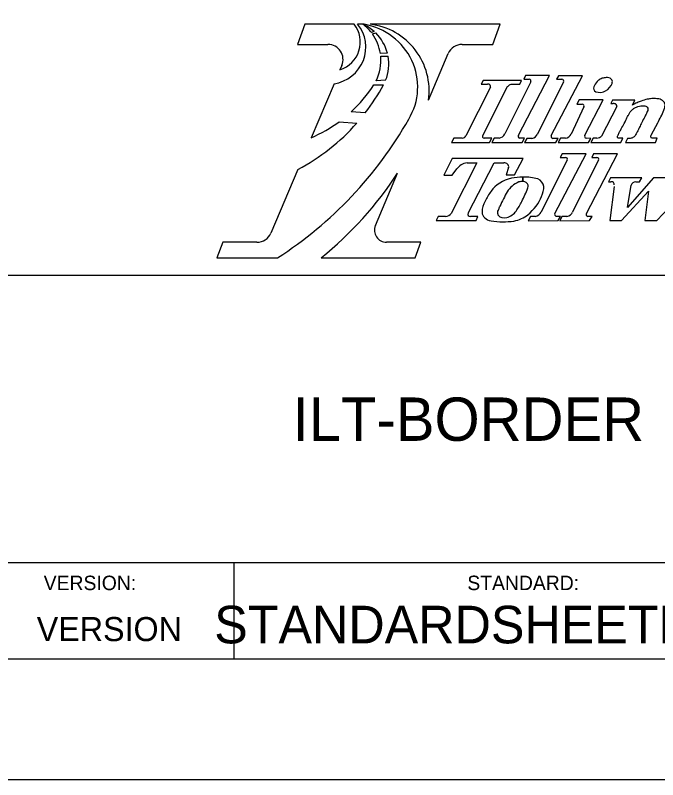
# Model space of a CAD drawing. Extents: x 0 to 2.83, y 0 to 1.83.
# Drawn here: x 2.4416 to 2.6636, y 0 to 0.2643 of the extents above; entities that cross this region are included whole.
import ezdxf

# ---------------------------------------------------------------- set-up
doc = ezdxf.new("R2010")
doc.units = 0
for name, color, linetype in [('SH_General_Details', 7, 'Continuous'), ('SH_General_Details_Sheet_Standard-ILTollway', 7, 'Continuous'), ('SH_General_Details_Title_Text-ILTollway', 7, 'Continuous'), ('SH_General_Details_Version_Text-ILTollway', 7, 'Continuous'), ('SH_Printer Plotting Border-ILTollway', 7, 'Continuous')]:
    doc.layers.add(name, color=color, linetype=linetype)

msp = doc.modelspace()

# ---------------------------------------------------------------- linework, layer by layer
at = {"layer": 'SH_General_Details'}
for p, q in [((2.541678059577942, 0.26125465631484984), (2.5391048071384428, 0.25424934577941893)), ((2.558770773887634, 0.26125307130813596), (2.541678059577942, 0.26125465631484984)), ((2.5617576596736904, 0.2612526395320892), (2.5599128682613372, 0.2612529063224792)), ((2.5622159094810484, 0.26125257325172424), (2.5617576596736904, 0.2612526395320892)), ((2.6092131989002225, 0.2612457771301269), (2.564246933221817, 0.26125227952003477)), ((2.6066432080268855, 0.25424934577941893), (2.6092131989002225, 0.2612457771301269)), ((2.5656805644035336, 0.2587088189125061), (2.564693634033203, 0.2583604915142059)), ((2.5650607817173, 0.2578687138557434), (2.5662091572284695, 0.25821166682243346)), ((2.5391048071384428, 0.25424934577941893), (2.5496910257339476, 0.25424934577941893)), ((2.5960569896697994, 0.25424934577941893), (2.6066432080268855, 0.25424934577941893)), ((2.570235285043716, 0.25119200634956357), (2.567815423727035, 0.251082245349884)), ((2.567924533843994, 0.2501808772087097), (2.5704507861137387, 0.25021086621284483)), ((2.584443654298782, 0.23498173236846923), (2.5912613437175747, 0.25107288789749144)), ((2.5544875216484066, 0.2470111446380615), (2.5538310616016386, 0.24545995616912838)), ((2.551788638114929, 0.24063379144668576), (2.5439024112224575, 0.221998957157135)), ((2.569615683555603, 0.24183801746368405), (2.5663216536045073, 0.24171894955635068)), ((2.616512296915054, 0.24179491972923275), (2.6032718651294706, 0.24179491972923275)), ((2.6197487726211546, 0.2413310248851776), (2.610752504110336, 0.22328553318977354)), ((2.615985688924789, 0.24053008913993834), (2.616512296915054, 0.24179491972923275)), ((2.6311086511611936, 0.24128882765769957), (2.622112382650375, 0.2232433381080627)), ((2.5655231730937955, 0.24031608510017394), (2.5688893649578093, 0.24028897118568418)), ((2.6058492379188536, 0.23947303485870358), (2.5973743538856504, 0.22265382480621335)), ((2.603179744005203, 0.22279209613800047), (2.6117820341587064, 0.23965211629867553)), ((2.613987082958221, 0.24053468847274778), (2.615985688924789, 0.24053008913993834)), ((2.6381201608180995, 0.23271397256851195), (2.633689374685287, 0.22326657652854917)), ((2.6494769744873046, 0.23273907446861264), (2.6442469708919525, 0.2225763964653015)), ((2.647989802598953, 0.2350050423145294), (2.6474070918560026, 0.23379013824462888)), ((2.6474070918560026, 0.23379013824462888), (2.648289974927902, 0.23379013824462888)), ((2.655788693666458, 0.2350050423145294), (2.647989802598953, 0.2350050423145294)), ((2.6549143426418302, 0.233294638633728), (2.655788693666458, 0.2350050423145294)), ((2.56256064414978, 0.23056123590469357), (2.5576849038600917, 0.23094110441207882)), ((2.5535774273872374, 0.22753960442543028), (2.559652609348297, 0.22704168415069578)), ((2.6615555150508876, 0.22308809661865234), (2.6636318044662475, 0.22710824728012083)), ((2.5931374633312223, 0.22180414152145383), (2.59234472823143, 0.22033744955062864)), ((2.59234472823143, 0.22033744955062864), (2.605503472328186, 0.22033744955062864)), ((2.5960391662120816, 0.2218161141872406), (2.5931374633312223, 0.22180414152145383)), ((2.6062812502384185, 0.22180450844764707), (2.603693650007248, 0.22180450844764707)), ((2.605503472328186, 0.22033744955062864), (2.6062812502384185, 0.22180450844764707)), ((2.607087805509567, 0.2218036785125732), (2.6062950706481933, 0.22033698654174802)), ((2.6062950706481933, 0.22033698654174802), (2.6168223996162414, 0.22032778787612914)), ((2.608808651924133, 0.2218008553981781), (2.607087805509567, 0.2218036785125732)), ((2.6176034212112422, 0.22180262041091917), (2.6160084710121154, 0.22181677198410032)), ((2.6168223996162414, 0.22032778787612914), (2.6176034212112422, 0.22180262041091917)), ((2.618447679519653, 0.2217614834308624), (2.6176549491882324, 0.22029479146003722)), ((2.6176549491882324, 0.22029479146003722), (2.6284404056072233, 0.22029142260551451)), ((2.6201685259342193, 0.22175866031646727), (2.618447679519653, 0.2217614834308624)), ((2.6292331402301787, 0.2217581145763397), (2.6273683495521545, 0.2217745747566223)), ((2.6284404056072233, 0.22029142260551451), (2.6292331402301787, 0.2217581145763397)), ((2.6300077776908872, 0.22183038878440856), (2.629215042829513, 0.22036369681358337)), ((2.629231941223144, 0.22031802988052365), (2.6397115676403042, 0.22031637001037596)), ((2.6317455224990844, 0.22178189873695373), (2.6300246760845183, 0.22178472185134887)), ((2.640502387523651, 0.22178071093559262), (2.6389453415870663, 0.22179781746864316)), ((2.6397115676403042, 0.22031637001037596), (2.640502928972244, 0.22178052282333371)), ((2.6412836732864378, 0.22180444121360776), (2.6404826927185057, 0.22033670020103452)), ((2.6404826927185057, 0.22033670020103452), (2.650853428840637, 0.22033670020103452)), ((2.642634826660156, 0.22180444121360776), (2.6412836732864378, 0.22180444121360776)), ((2.6515525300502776, 0.221801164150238), (2.6502094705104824, 0.221801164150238)), ((2.650853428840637, 0.22033670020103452), (2.6515525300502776, 0.221801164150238)), ((2.6531976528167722, 0.22174590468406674), (2.652547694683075, 0.22033670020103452)), ((2.652547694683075, 0.22033670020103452), (2.662856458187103, 0.22033670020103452)), ((2.6634214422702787, 0.2218007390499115), (2.6617628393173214, 0.22181180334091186)), ((2.662856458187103, 0.22033670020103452), (2.6634214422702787, 0.2218007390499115)), ((2.6323300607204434, 0.21430038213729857), (2.6233337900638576, 0.19625489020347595)), ((2.6432246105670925, 0.21430038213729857), (2.6342283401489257, 0.19625489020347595)), ((2.598115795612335, 0.1958784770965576), (2.6070817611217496, 0.2133110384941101)), ((2.6070817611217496, 0.2133110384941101), (2.610442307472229, 0.2133110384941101)), ((2.5392720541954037, 0.21105761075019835), (2.529944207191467, 0.18901628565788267)), ((2.5660758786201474, 0.19162998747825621), (2.573748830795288, 0.20973973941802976)), ((2.592641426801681, 0.20907231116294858), (2.594264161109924, 0.21120603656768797)), ((2.6170039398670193, 0.2083940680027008), (2.6170039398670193, 0.20687558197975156)), ((2.6170039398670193, 0.20687558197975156), (2.6170039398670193, 0.2083940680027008)), ((2.6666739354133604, 0.2080908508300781), (2.6621581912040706, 0.2080908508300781)), ((2.663346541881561, 0.19334409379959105), (2.6746359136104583, 0.20542692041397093)), ((2.6196690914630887, 0.19477303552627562), (2.6188763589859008, 0.193306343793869)), ((2.6188763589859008, 0.193306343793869), (2.6292116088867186, 0.19333077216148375)), ((2.6213899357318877, 0.19477021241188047), (2.6196690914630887, 0.19477303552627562)), ((2.630071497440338, 0.19479352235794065), (2.6285897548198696, 0.1947861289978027)), ((2.6292116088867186, 0.19333077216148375), (2.630071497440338, 0.19479352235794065)), ((2.6305636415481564, 0.19477303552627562), (2.6297709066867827, 0.193306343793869)), ((2.6297709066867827, 0.193306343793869), (2.6401061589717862, 0.19333077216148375)), ((2.6322844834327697, 0.19477021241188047), (2.6305636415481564, 0.19477303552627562)), ((2.6409660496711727, 0.19479352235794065), (2.639484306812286, 0.1947861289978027)), ((2.6401061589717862, 0.19333077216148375), (2.6409660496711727, 0.19479352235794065)), ((2.6591873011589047, 0.19334409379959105), (2.663346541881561, 0.19334409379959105)), ((2.513288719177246, 0.18583782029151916), (2.5113223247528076, 0.1804845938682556)), ((2.5251477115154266, 0.18583782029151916), (2.513288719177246, 0.18583782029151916)), ((2.581771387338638, 0.18583782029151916), (2.5699123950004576, 0.18583782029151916)), ((2.579804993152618, 0.1804845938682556), (2.581771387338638, 0.18583782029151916)), ((2.5113223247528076, 0.1804845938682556), (2.53227757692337, 0.1804845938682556)), ((2.547344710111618, 0.1804845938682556), (2.579804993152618, 0.1804845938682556)), ((2.7916666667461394, 0.17433751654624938), (2.4316674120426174, 0.17433751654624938)), ((2.7916666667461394, 0.07499986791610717), (2.4316674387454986, 0.07499986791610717)), ((2.517257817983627, 0.04166668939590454), (2.517257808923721, 0.07499986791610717))]:
    msp.add_line(p, q, dxfattribs=at)
msp.add_lwpolyline([(0.1666666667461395, 0.0416666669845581), (0.1666666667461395, 1.791666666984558), (2.7916666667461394, 1.791666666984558), (2.7916666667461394, 0.0416666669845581)], close=True, dxfattribs=at)
for points in [[(2.6155131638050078, 0.22285597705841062), (2.6262976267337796, 0.2434896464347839), (2.61800227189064, 0.2434869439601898)], [(2.61800227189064, 0.2434869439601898), (2.6173446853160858, 0.24223627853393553), (2.6191797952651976, 0.24223627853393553)], [(2.626873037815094, 0.22281378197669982), (2.6376575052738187, 0.24344744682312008), (2.629362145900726, 0.24344474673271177)], [(2.629362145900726, 0.24344474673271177), (2.628704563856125, 0.2421940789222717)], [(2.5663006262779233, 0.2417181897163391), (2.5663148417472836, 0.24171870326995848), (2.5663184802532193, 0.24171883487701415)], [(2.5663216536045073, 0.24171894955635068), (2.5663150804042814, 0.2417120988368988)], [(2.5663184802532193, 0.24171883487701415), (2.5663216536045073, 0.24171894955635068)], [(2.6032718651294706, 0.24179491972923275), (2.6026142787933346, 0.2405442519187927)], [(2.6026142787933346, 0.2405442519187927), (2.6048686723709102, 0.2405442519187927)], [(2.628704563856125, 0.2421940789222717), (2.6305396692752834, 0.2421940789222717)], [(2.636509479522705, 0.23505239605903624), (2.6357160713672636, 0.23361922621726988), (2.6375511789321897, 0.23361922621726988)], [(2.638450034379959, 0.22283702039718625), (2.644804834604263, 0.23505509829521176), (2.636509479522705, 0.23505239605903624)], [(2.612125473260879, 0.21171108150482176), (2.6113013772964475, 0.20911943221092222), (2.6141857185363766, 0.20911943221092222), (2.6171877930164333, 0.21477393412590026), (2.5925825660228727, 0.21477393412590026), (2.5896982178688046, 0.20907231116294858), (2.592641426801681, 0.20907231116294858)], [(2.6280944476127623, 0.19582533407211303), (2.6388789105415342, 0.21645900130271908), (2.6305835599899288, 0.21645630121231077)], [(2.6305835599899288, 0.21645630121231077), (2.629925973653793, 0.2152056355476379), (2.6317610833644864, 0.2152056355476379)], [(2.6389889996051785, 0.19582533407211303), (2.649773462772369, 0.21645900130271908), (2.641478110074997, 0.21645630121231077)], [(2.641478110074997, 0.21645630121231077), (2.6408205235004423, 0.2152056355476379), (2.6426556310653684, 0.2152056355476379)], [(2.5977626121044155, 0.21331319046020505), (2.601117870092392, 0.21331319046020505), (2.592229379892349, 0.19583135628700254)], [(2.6473037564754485, 0.20813842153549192), (2.64659074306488, 0.20675888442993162), (2.6474820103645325, 0.20675888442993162)], [(2.6560975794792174, 0.20675888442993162), (2.657345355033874, 0.20675888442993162), (2.6581772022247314, 0.20813842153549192), (2.6473037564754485, 0.20813842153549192)], [(2.6621581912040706, 0.2080908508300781), (2.6531861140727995, 0.1979108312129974)], [(2.6485515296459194, 0.20509393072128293), (2.6471255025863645, 0.19334409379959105), (2.651165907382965, 0.19334409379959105)], [(2.6531861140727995, 0.1979108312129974), (2.6544338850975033, 0.20561720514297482)], [(2.651165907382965, 0.19334409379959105), (2.660435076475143, 0.20352411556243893), (2.6591873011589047, 0.19334409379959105)], [(2.5902868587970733, 0.19474757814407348), (2.5877556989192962, 0.19474757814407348), (2.5871081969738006, 0.19333395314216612), (2.6008824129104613, 0.19333395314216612), (2.601529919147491, 0.19474757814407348), (2.5989987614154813, 0.19474757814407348)]]:
    msp.add_lwpolyline(points, dxfattribs=at)
for centre, radius, start, end in [((2.5507281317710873, 0.255099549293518), 0.010126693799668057, 287.8430702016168, 37.42003830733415), ((2.5556024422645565, 0.24746375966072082), 0.01510032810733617, 48.13245664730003, 65.94449523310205), ((2.5523351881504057, 0.24875107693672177), 0.015654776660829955, 37.86715463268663, 52.99453830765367), ((2.5614015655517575, 0.23816590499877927), 0.02326105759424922, 352.1321590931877, 82.97379849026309), ((2.5523351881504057, 0.24875107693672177), 0.015654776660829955, 8.563821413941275, 35.620851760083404), ((2.5556024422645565, 0.24746375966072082), 0.01510032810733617, 14.2940508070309, 45.378821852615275), ((2.5496910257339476, 0.24904101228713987), 0.005208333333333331, 337.0620105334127, 90), ((2.5960569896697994, 0.24904101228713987), 0.005208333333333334, 89.99999999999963, 157.0380282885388), ((2.5523351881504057, 0.24875107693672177), 0.015654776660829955, 333.3076244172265, 5.240307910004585), ((2.5556024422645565, 0.24746375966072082), 0.01510032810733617, 338.1265619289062, 10.481826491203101), ((2.5249901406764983, 0.26624088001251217), 0.04811467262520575, 312.80595253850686, 327.3971515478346), ((2.506296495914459, 0.2740884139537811), 0.07113557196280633, 322.2736785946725, 331.63145455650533), ((2.4574629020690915, 0.29661533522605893), 0.13814334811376, 302.79076806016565, 330.41292215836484), ((2.5249901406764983, 0.26624088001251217), 0.04811467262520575, 293.1454474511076, 306.45199352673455), ((2.506296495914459, 0.2740884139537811), 0.07113557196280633, 297.6170242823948, 318.5957779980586), ((2.469345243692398, 0.2774257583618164), 0.1244247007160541, 308.8203728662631, 327.04420513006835), ((2.5699123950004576, 0.19000448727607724), 0.004166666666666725, 157.03802828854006, 270), ((2.5251477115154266, 0.1910461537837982), 0.005208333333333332, 270.00000000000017, 337.0620105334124)]:
    msp.add_arc(centre, radius, start, end, dxfattribs=at)
for centre, major_axis, ratio, start_param, end_param in [((2.5495658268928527, 0.2532761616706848), (0.0132138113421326, 0), 0.9705854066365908, 4.8814113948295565, 6.954431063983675), ((2.5579672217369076, 0.23956523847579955), (0.022744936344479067, 0), 0.9705854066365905, 5.75331709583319, 7.666080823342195), ((2.566307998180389, 0.24171546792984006), (7.887166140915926e-06, 0), 0.9705854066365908, 2.778111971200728, 5.827459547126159), ((2.604906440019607, 0.23974349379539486), (0.0010015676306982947, -2.4531331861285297e-19), 0.8000752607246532, 5.938912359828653, 7.891702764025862), ((2.6190690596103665, 0.2416246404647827), (0.0007724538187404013, -1.8919661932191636e-19), 0.800075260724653, 5.788124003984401, 7.71013160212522), ((2.6304289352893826, 0.2415824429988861), (0.0007724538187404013, -1.8919661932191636e-19), 0.800075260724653, 5.788124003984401, 7.71013160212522), ((2.649391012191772, 0.2375553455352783), (-0.008237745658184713, 1.0088328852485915e-18), 0.8000752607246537, 5.657384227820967, 5.961923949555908), ((2.641774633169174, 0.24230186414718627), (0.006436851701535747, -1.5765739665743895e-18), 0.8000752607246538, 5.35994097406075, 5.975474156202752), ((2.643243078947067, 0.2390981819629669), (-0.00179891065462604, 2.2030301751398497e-19), 0.8000752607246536, 5.899852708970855, 7.2592592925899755), ((2.6436369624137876, 0.24040055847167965), (-0.003418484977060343, 4.1864366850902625e-19), 0.800075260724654, 1.1482793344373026, 2.20319774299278), ((2.637440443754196, 0.23300758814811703), (0.0007724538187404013, -1.8919661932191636e-19), 0.800075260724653, 5.788124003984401, 7.71013160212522), ((2.6484939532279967, 0.23298302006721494), (-0.0010292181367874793, 1.2604286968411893e-19), 0.8000752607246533, 2.840833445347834, 4.911898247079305), ((2.5958096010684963, 0.2231503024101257), (0.0016833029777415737, -4.122903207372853e-19), 0.8000752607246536, 4.8491919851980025, 5.905635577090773), ((2.603823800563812, 0.22242724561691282), (-0.0007891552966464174, 9.664365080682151e-20), 0.8000752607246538, 5.667079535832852, 7.688297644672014), ((2.607959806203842, 0.2240691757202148), (0.0029594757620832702, -7.2486250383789e-19), 0.8000752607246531, 5.00329646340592, 5.945866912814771), ((2.6163459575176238, 0.22251490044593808), (-0.0009355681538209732, 1.1457405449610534e-19), 0.8000752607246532, 5.810064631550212, 7.4849317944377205), ((2.619319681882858, 0.22402697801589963), (0.0029594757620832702, -7.2486250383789e-19), 0.8000752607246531, 5.00329646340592, 5.945866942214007), ((2.6277058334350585, 0.2224727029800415), (-0.0009355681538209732, 1.1457405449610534e-19), 0.8000752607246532, 5.810064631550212, 7.48493146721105), ((2.6308966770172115, 0.22405021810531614), (0.0029594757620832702, -7.2486250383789e-19), 0.8000752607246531, 5.003296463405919, 5.945867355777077), ((2.6392828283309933, 0.222495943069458), (-0.0009355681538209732, 1.1457405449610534e-19), 0.8000752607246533, 5.810064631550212, 7.484931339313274), ((2.6421507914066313, 0.22391506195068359), (0.00268206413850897, -6.569162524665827e-19), 0.8000752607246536, 4.893854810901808, 5.609542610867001), ((2.6316503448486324, 0.21459399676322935), (0.0007724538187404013, -1.8919661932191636e-19), 0.800075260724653, 5.788124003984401, 7.71013160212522), ((2.6425448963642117, 0.2145939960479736), (0.0007724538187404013, -1.8919661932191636e-19), 0.800075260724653, 5.788124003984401, 7.71013160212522), ((2.5988792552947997, 0.20921383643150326), (-0.005243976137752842, 6.422018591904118e-19), 0.8000752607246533, 4.92697049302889, 5.7884101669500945), ((2.6104337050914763, 0.2119385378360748), (0.0017154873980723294, -4.201732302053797e-19), 0.8000752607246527, 6.116694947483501, 7.848967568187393), ((2.616626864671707, 0.19869619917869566), (-0.012129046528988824, 1.4853798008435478e-18), 0.8000752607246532, 5.01078761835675, 5.765691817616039), ((2.6195860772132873, 0.2004766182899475), (-0.008689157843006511, 1.0641149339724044e-18), 0.8000752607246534, 5.175654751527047, 5.860096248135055), ((2.6171590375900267, 0.19548105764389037), (-0.016140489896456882, 1.9766399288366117e-18), 0.8000752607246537, 4.721998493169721, 4.969094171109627), ((2.6167585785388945, 0.20490928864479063), (-0.0024698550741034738, 3.024700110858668e-19), 0.8000752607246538, 4.612883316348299, 5.153926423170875), ((2.6171590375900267, 0.19548105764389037), (-0.016140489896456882, 1.9766399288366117e-18), 0.8000383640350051, 4.395078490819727, 4.7149049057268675), ((2.6167585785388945, 0.20490928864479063), (-0.0024698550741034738, 3.024700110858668e-19), 0.8000752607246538, 4.071840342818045, 4.566171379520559), ((2.616702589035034, 0.20525218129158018), (0.002180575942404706, -5.340870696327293e-19), 0.8000752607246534, 5.909204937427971, 7.074943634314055), ((2.620201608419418, 0.20487194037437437), (0.004112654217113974, -1.0073097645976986e-18), 0.8000752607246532, 0.08712246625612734, 1.0647598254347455), ((2.6475526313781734, 0.20587112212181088), (-0.0011118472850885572, 1.3616202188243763e-19), 0.8000752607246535, 2.93516670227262, 4.775951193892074), ((2.6561704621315, 0.20534410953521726), (-0.0017698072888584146, 2.1673888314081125e-19), 0.800075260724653, 4.753581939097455, 6.089103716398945), ((2.565342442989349, 0.21723486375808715), (0.0556713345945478, -1.3635544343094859e-17), 0.8000752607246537, 5.883899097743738, 5.995916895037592), ((2.611839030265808, 0.20521104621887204), (0.012459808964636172, -3.051773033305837e-18), 0.8000752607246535, 5.922241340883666, 6.277888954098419), ((2.6329956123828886, 0.19068926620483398), (-0.03131109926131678, 3.8345037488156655e-18), 0.8000752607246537, 5.7465390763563, 5.900046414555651), ((2.7141161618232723, 0.16679252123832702), (-0.11217070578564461, 1.3736949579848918e-17), 0.8000752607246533, 5.863868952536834, 5.924634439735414), ((2.6045524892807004, 0.20649450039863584), (0.019872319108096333, -4.867314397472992e-18), 0.8000752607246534, 5.5091350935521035, 5.976236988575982), ((2.613942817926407, 0.19639452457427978), (-0.01098572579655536, 1.3453633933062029e-18), 0.8000752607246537, 5.853724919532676, 6.297771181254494), ((2.5899682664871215, 0.20798209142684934), (0.028507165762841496, -6.98224186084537e-18), 0.8000752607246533, 5.76243947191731, 5.92185011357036), ((2.590139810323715, 0.19657253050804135), (0.0022857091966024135, -5.598372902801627e-19), 0.8000752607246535, 4.776767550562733, 5.865888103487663), ((2.598944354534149, 0.19550648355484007), (-0.000950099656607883, 1.1635365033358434e-19), 0.8000752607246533, 5.771816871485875, 7.911274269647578), ((2.606946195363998, 0.1963254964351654), (-0.0039886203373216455, 4.88465112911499e-19), 0.8000752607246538, 0.018542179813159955, 1.3534190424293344), ((2.609394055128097, 0.19890387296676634), (0.006013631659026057, -1.4729149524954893e-18), 0.8000752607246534, 5.063271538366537, 5.7920136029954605), ((2.6205410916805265, 0.19703853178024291), (0.0029594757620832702, -7.2486250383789e-19), 0.8000752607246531, 5.00329646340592, 5.945867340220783), ((2.6289272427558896, 0.19548425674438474), (-0.0009355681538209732, 1.1457405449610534e-19), 0.8000752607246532, 5.810064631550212, 7.484931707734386), ((2.6314356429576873, 0.19703853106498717), (0.0029594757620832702, -7.2486250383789e-19), 0.8000752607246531, 5.00329646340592, 5.945867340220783), ((2.6398217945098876, 0.19548425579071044), (-0.0009355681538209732, 1.1457405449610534e-19), 0.8000752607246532, 5.810064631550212, 7.484931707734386), ((2.610179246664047, 0.21168625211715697), (0.023453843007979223, -5.744534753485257e-18), 0.8000752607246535, 4.536965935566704, 4.873723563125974), ((2.6105971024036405, 0.1961409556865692), (-0.002357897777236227, 2.887591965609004e-19), 0.8000752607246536, 0.5153538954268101, 1.9459629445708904), ((2.611501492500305, 0.2010271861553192), (0.010126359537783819, -2.480242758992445e-18), 0.8000752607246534, 4.9562759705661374, 5.511991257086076)]:
    msp.add_ellipse(centre, major_axis=major_axis, ratio=ratio, start_param=start_param, end_param=end_param, dxfattribs=at)
for points in [[(2.647909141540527, 0.24074205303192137), (2.647969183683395, 0.24139097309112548), (2.6477590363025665, 0.24203988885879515), (2.6471586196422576, 0.2426167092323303), (2.646257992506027, 0.2427609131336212), (2.644786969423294, 0.24264074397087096), (2.6434360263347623, 0.2420158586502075), (2.642714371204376, 0.24141589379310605)], [(2.6117820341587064, 0.23965211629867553), (2.6127008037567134, 0.24036657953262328), (2.613987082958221, 0.24053468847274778)], [(2.6636318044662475, 0.22710824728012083), (2.665756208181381, 0.2314826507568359), (2.6661532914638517, 0.23283391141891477), (2.6660341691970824, 0.23399440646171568), (2.665835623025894, 0.23431235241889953), (2.665279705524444, 0.23483696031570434), (2.664465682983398, 0.23528208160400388), (2.662897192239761, 0.23552054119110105), (2.66228171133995, 0.2355682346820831), (2.6615669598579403, 0.23550464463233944), (2.660038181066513, 0.23528208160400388), (2.657933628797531, 0.23466209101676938), (2.6565209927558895, 0.23410625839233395), (2.6549143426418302, 0.233294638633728)], [(2.6528441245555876, 0.22856152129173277), (2.6533814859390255, 0.22962547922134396), (2.653890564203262, 0.23045174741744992), (2.654413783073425, 0.2313006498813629), (2.6549087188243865, 0.2317194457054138), (2.6557713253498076, 0.23235329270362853), (2.65683190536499, 0.232783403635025), (2.6577793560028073, 0.23299845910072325), (2.658585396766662, 0.23305505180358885), (2.659207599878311, 0.23297582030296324), (2.6597449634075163, 0.2327381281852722), (2.6600136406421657, 0.23252307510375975), (2.660282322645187, 0.231855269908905), (2.6599853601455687, 0.23105163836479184), (2.6594762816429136, 0.2297952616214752), (2.658910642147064, 0.22871998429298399)], [(2.6502094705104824, 0.221801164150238), (2.6500305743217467, 0.22187633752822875), (2.649816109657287, 0.22199984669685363), (2.6497217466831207, 0.22226745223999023), (2.6497732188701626, 0.222569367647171), (2.6499734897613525, 0.22291086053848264), (2.6502280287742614, 0.22347679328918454), (2.650737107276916, 0.22454075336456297), (2.651811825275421, 0.22644229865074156), (2.6528441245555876, 0.22856152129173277)], [(2.658910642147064, 0.22871998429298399), (2.6579490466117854, 0.22679405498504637), (2.6571571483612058, 0.22518679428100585), (2.656336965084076, 0.22360217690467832), (2.656025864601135, 0.2230136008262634), (2.6557713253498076, 0.2225608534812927), (2.6552622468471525, 0.22213074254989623), (2.6548945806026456, 0.221949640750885), (2.6544420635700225, 0.22179118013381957), (2.6531976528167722, 0.22174590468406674)], [(2.6617628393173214, 0.22181180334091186), (2.6615458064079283, 0.2218943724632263), (2.6612639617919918, 0.22218026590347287), (2.6613205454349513, 0.22258625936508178), (2.6615555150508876, 0.22308809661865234)], [(2.6085454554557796, 0.195211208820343), (2.6084574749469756, 0.1954600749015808), (2.608442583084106, 0.19656918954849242), (2.608710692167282, 0.19726089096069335), (2.609078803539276, 0.19828562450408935)]]:
    msp.add_spline(points, degree=3, dxfattribs=at)
at = {"layer": 'SH_Printer Plotting Border-ILTollway'}
msp.add_lwpolyline([(0, 1.833282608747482), (2.833327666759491, 1.833282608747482), (2.833327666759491, 0), (0, 0)], close=True, dxfattribs=at)

# ---------------------------------------------------------------- texts
at = {"layer": 'SH_General_Details'}
for s, p in [('VERSION:', (2.45144259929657, 0.06555551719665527)), ('STANDARD:', (2.5978434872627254, 0.06555551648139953))]:
    msp.add_text(s, height=0.004999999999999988, rotation=1.0784289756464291e-05, dxfattribs=at).set_placement(p)
at = {"layer": 'SH_General_Details_Sheet_Standard-ILTollway'}
msp.add_text('STANDARDSHEETBORDER', height=0.013, dxfattribs=at).set_placement((2.510364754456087, 0.047145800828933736))
at = {"layer": 'SH_General_Details_Title_Text-ILTollway'}
msp.add_text('ILT-BORDER', height=0.014999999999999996, dxfattribs=at).set_placement((2.5374648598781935, 0.11716869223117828))
at = {"layer": 'SH_General_Details_Version_Text-ILTollway'}
msp.add_text('VERSION', height=0.008333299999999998, dxfattribs=at).set_placement((2.449036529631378, 0.047916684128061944))

doc.saveas('drawing.dxf')
